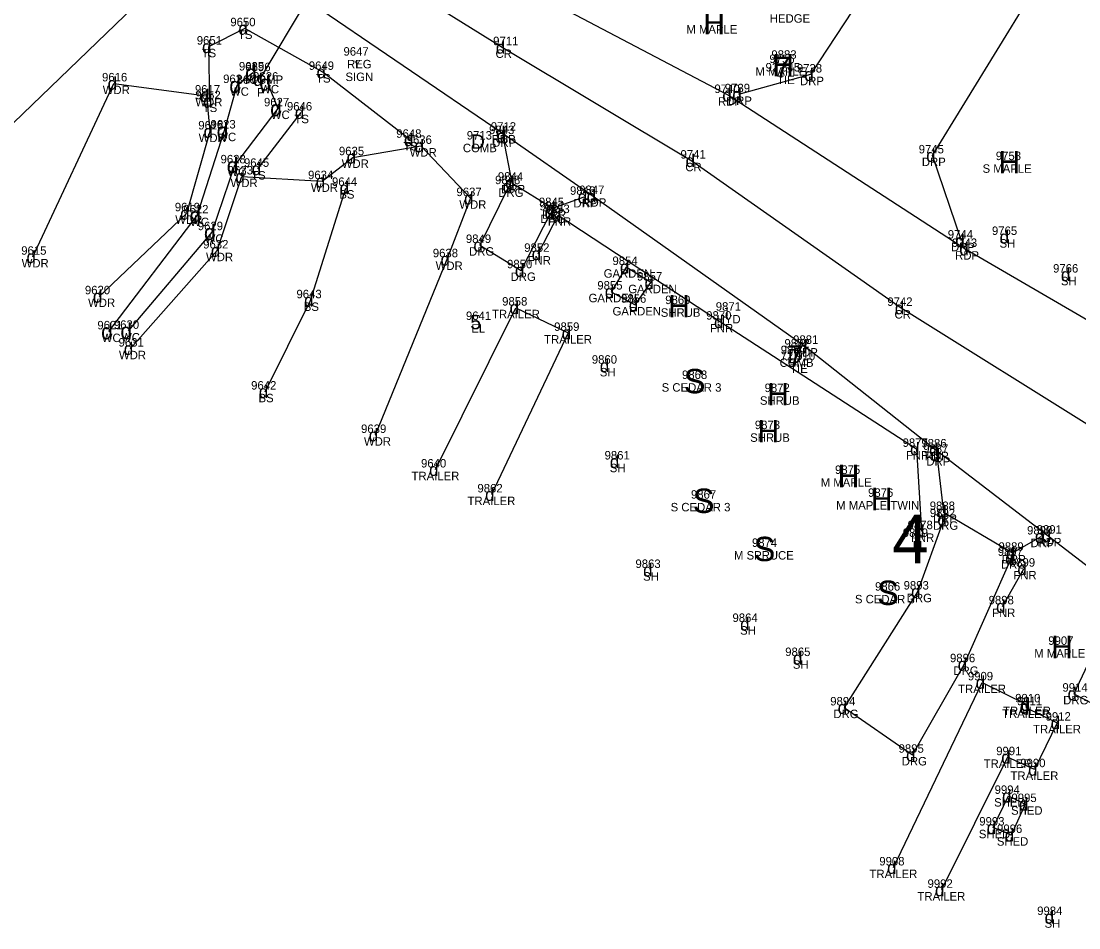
# Model space of a CAD drawing. Extents: x 69415 to 80913, y 7576 to 15059.
# Drawn here: x 78709.2 to 78958.8, y 12276.2 to 12490.3 of the extents above; entities that cross this region are included whole.
import ezdxf

# ---------------------------------------------------------------- set-up
doc = ezdxf.new("R2010")
doc.units = 0
for name, color, linetype in [('Level 1', 7, 'Continuous'), ('Level 11', 7, 'Continuous'), ('Level 12', 7, 'Continuous'), ('Level 13', 7, 'Continuous'), ('Level 14', 7, 'Continuous'), ('Level 15', 7, 'Continuous'), ('Level 16', 7, 'Continuous'), ('Level 43', 7, 'Continuous'), ('Level 46', 7, 'Continuous'), ('Level 47', 7, 'Continuous'), ('Level 48', 7, 'Continuous'), ('Level 59', 7, 'Continuous')]:
    doc.layers.add(name, color=color, linetype=linetype)

msp = doc.modelspace()

# ---------------------------------------------------------------- linework, layer by layer
at = {"layer": 'Level 11'}
for p, q in [((78830.44, 12496.88), (78876.16, 12472.86)), ((78908.51, 12497.6), (78895.52, 12477.7)), ((78924.29, 12458.6), (78948.44, 12498.05)), ((78775.93, 12495.84), (78822.71, 12463.96)), ((78895.52, 12477.7), (78878.52, 12473.04)), ((78876.16, 12472.86), (78932.13, 12436.51)), ((78822.71, 12463.96), (78844.14, 12449.01)), ((78822.87, 12463.15), (78824.95, 12452.16)), ((78931.15, 12438.49), (78924.29, 12458.6)), ((78824.29, 12451.34), (78817.41, 12437.45)), ((78824.95, 12452.16), (78834.62, 12446.16)), ((78834.62, 12446.16), (78842.03, 12448.83)), ((78844.14, 12449.01), (78894.07, 12413.63)), ((78827.2, 12431.48), (78834.2, 12445.15)), ((78817.41, 12437.45), (78827.2, 12431.48)), ((78932.13, 12436.51), (78963.41, 12418.3)), ((78894.07, 12413.63), (78924.98, 12389.17)), ((78924.98, 12389.17), (78951.57, 12368.82)), ((78925.34, 12387.89), (78926.89, 12374.4)), ((78926.89, 12374.4), (78943.13, 12364.78)), ((78926.92, 12372.73), (78920.72, 12355.62)), ((78943.13, 12364.78), (78949.94, 12368.62)), ((78951.57, 12368.82), (78966.36, 12357.45)), ((78931.73, 12338.46), (78942.94, 12363.58)), ((78920.72, 12355.62), (78903.4, 12328.26)), ((78964.1, 12345.2), (78957.65, 12331.51)), ((78919.54, 12317.09), (78931.73, 12338.46)), ((78957.65, 12331.51), (78966.28, 12326.96)), ((78903.4, 12328.26), (78919.54, 12317.09))]:
    msp.add_line(p, q, dxfattribs=at)
at = {"layer": 'Level 12'}
for p, q in [((78831.16, 12435.36), (78835.95, 12444.51)), ((78835.95, 12444.51), (78874.21, 12419.34)), ((78851.99, 12432.25), (78848.42, 12426.45)), ((78857.79, 12428.58), (78851.99, 12432.25)), ((78848.42, 12426.45), (78854.08, 12423.34)), ((78854.08, 12423.34), (78857.79, 12428.58)), ((78874.21, 12419.34), (78920.48, 12389.31)), ((78920.48, 12389.31), (78921.66, 12369.87)), ((78940.79, 12352.13), (78945.82, 12361.02))]:
    msp.add_line(p, q, dxfattribs=at)
at = {"layer": 'Level 13'}
for p, q in [((78806.95, 12384.44), (78825.95, 12422.67)), ((78825.95, 12422.67), (78838.25, 12416.7)), ((78838.25, 12416.7), (78820.17, 12378.55)), ((78915.06, 12290.48), (78935.98, 12334.18)), ((78935.98, 12334.18), (78946.58, 12328.98)), ((78946.58, 12328.98), (78946.35, 12328.31)), ((78946.35, 12328.31), (78953.68, 12324.67)), ((78953.68, 12324.67), (78948.35, 12313.67)), ((78942.01, 12316.51), (78926.37, 12285.2)), ((78948.35, 12313.67), (78942.01, 12316.51)), ((78938.58, 12299.9), (78942.2, 12307.38)), ((78942.2, 12307.38), (78946.18, 12305.45)), ((78946.18, 12305.45), (78942.83, 12298.15)), ((78942.83, 12298.15), (78938.58, 12299.9))]:
    msp.add_line(p, q, dxfattribs=at)
at = {"layer": 'Level 14'}
for p, q in [((78711.91, 12434.67), (78731.05, 12475.6)), ((78731.05, 12475.6), (78752.91, 12472.73)), ((78752.91, 12472.73), (78753.7, 12464.26)), ((78753.7, 12464.26), (78748.18, 12444.94)), ((78787.47, 12458.17), (78803.51, 12460.85)), ((78803.51, 12460.85), (78815.21, 12448.52)), ((78780.19, 12452.52), (78787.47, 12458.17)), ((78755.43, 12436.15), (78761.23, 12453.63)), ((78761.23, 12453.63), (78780.19, 12452.52)), ((78815.21, 12448.52), (78809.64, 12434.08)), ((78748.18, 12444.94), (78727.59, 12425.34)), ((78734.88, 12412.99), (78755.43, 12436.15)), ((78809.64, 12434.08), (78792.7, 12392.59))]:
    msp.add_line(p, q, dxfattribs=at)
at = {"layer": 'Level 15'}
msp.add_line((78753.41, 12510.83), (78705.11, 12464.18), dxfattribs=at)
at = {"layer": 'Level 16'}
for p, q in [((78760.14, 12475.21), (78763.86, 12478.18)), ((78757.14, 12464.48), (78760.14, 12475.21)), ((78767.27, 12475.77), (78769.78, 12469.71)), ((78769.78, 12469.71), (78759.53, 12456.25)), ((78750.72, 12444.43), (78757.14, 12464.48)), ((78759.53, 12456.25), (78754.16, 12440.47)), ((78729.88, 12417.05), (78750.72, 12444.43)), ((78754.16, 12440.47), (78734.43, 12417.18))]:
    msp.add_line(p, q, dxfattribs=at)
at = {"layer": 'Level 48'}
for p, q in [((78784.6, 12507.97), (78822.7, 12484.15)), ((78761.93, 12488.62), (78753.35, 12484.29)), ((78780.37, 12478.32), (78761.93, 12488.62)), ((78753.35, 12484.29), (78753.61, 12471.37)), ((78822.7, 12484.15), (78867.49, 12457.38)), ((78801, 12462.29), (78780.37, 12478.32)), ((78765.05, 12455.43), (78775.25, 12468.73)), ((78867.49, 12457.38), (78916.88, 12422.6)), ((78777.44, 12424.4), (78785.82, 12450.93)), ((78766.75, 12402.84), (78777.44, 12424.4)), ((78916.88, 12422.6), (79048.1, 12340.71))]:
    msp.add_line(p, q, dxfattribs=at)
at = {"layer": 'Level 59'}
msp.add_line((78803.72, 12540.95), (78765.44, 12476.52), dxfattribs=at)

# ---------------------------------------------------------------- texts
at = {"layer": 'Level 1'}
for p in [(78887.01, 12476.95), (78890.09, 12408.77)]:
    msp.add_text('7', height=5, dxfattribs=at).set_placement(p)
at = {"layer": 'Level 14'}
for s, height, p in [('H', 5.3, (78870.17, 12487.25)), ('H', 5.3, (78886.45, 12477.29)), ('H', 5.3, (78939.84, 12454.37)), ('H', 5.3, (78861.86, 12420.37)), ('S', 5.75, (78865.58, 12402.46)), ('H', 5.3, (78885.26, 12399.6)), ('H', 5.3, (78882.96, 12390.85)), ('H', 5.3, (78901.88, 12380.27)), ('S', 5.75, (78867.7, 12374.21)), ('H', 5.3, (78909.73, 12374.86)), ('S', 5.75, (78882.05, 12362.83)), ('S', 5.75, (78911.2, 12352.48)), ('H', 5.3, (78952.3, 12339.91))]:
    msp.add_text(s, height=height, dxfattribs=at).set_placement(p)
at = {"layer": 'Level 15'}
for s, height, p in [('D', 3.4, (78815.33, 12460.18)), ('J', 2.26, (78874.68, 12420.33)), ('5', 3.4, (78815.18, 12417.57)), ('D', 3.4, (78890.1, 12409.5)), ('4', 11.5, (78914.79, 12362.3))]:
    msp.add_text(s, height=height, dxfattribs=at).set_placement(p)
at = {"layer": 'Level 43'}
msp.add_text('Y', height=1.7, dxfattribs=at).set_placement((78787.7, 12479.33))
at = {"layer": 'Level 46'}
for s, p in [('HEDGE', (78885.87, 12489.96)), ('9650', (78758.53, 12489.12)), ('M MAPLE', (78866.17, 12487.4)), ('9651', (78750.61, 12484.79)), ('TS', (78760.34, 12486.12)), ('9711', (78820.57, 12484.65)), ('TS', (78751.76, 12481.79)), ('9647', (78785.24, 12482.18)), ('CR', (78821.13, 12481.65)), ('9756', (78885.79, 12480.44)), ('9883', (78886.25, 12481.45)), ('9625', (78760.55, 12478.68)), ('9696', (78762.08, 12478.52)), ('9649', (78777.05, 12478.82)), ('REG', (78786.08, 12479.18)), ('M MAPLE', (78882.46, 12477.44)), ('92.345', (78884.87, 12478.45)), ('9738', (78892.26, 12478.2)), ('9616', (78728.25, 12476.1)), ('9624', (78756.83, 12475.71)), ('36CGMP', (78760.01, 12475.52)), ('WC', (78762.17, 12475.68)), ('9626', (78763.91, 12476.27)), ('TS', (78778.78, 12475.82)), ('SIGN', (78785.71, 12476.18)), ('TIE', (78887.59, 12475.45)), ('DRP', (78893.01, 12475.2)), ('WDR', (78728.41, 12473.1)), ('9617', (78750.17, 12473.23)), ('9652', (78750.3, 12471.87)), ('WC', (78758.45, 12472.71)), ('P', (78764.82, 12472.52)), ('WC', (78765.58, 12473.27)), ('9740', (78872.81, 12473.36)), ('9739', (78875.26, 12473.54)), ('WDR', (78750.27, 12470.23)), ('9627', (78766.47, 12470.21)), ('RDP', (78873.65, 12470.36)), ('DRP', (78876.01, 12470.54)), ('TS', (78752.02, 12468.87)), ('WC', (78768.09, 12467.21)), ('9646', (78771.89, 12469.23)), ('9618', (78750.96, 12464.76)), ('9623', (78753.84, 12464.98)), ('TS', (78773.66, 12466.23)), ('9712', (78820.02, 12464.46)), ('WC', (78755.45, 12461.98)), ('9648', (78797.69, 12462.79)), ('9713', (78814.34, 12462.38)), ('9843', (78819.61, 12463.65)), ('WDR', (78751.06, 12461.76)), ('TS', (78799.41, 12459.79)), ('9636', (78800.15, 12461.35)), ('COMB', (78813.42, 12459.38)), ('RDP', (78820.2, 12461.46)), ('DRP', (78820.36, 12460.65)), ('9635', (78784.16, 12458.67)), ('WDR', (78800.87, 12458.35)), ('9741', (78864.8, 12457.88)), ('9745', (78921.03, 12459.1)), ('9758', (78939.23, 12457.52)), ('9628', (78756.22, 12456.75)), ('9645', (78761.74, 12455.93)), ('WDR', (78784.83, 12455.67)), ('CR', (78865.93, 12454.88)), ('DRP', (78921.77, 12456.1)), ('S MAPLE', (78936.1, 12454.52)), ('WC', (78757.84, 12453.75)), ('9633', (78757.92, 12454.13)), ('TS', (78763.46, 12452.93)), ('9634', (78776.88, 12453.02)), ('9848', (78821.03, 12451.84)), ('9844', (78821.69, 12452.66)), ('WDR', (78758.59, 12451.13)), ('WDR', (78777.55, 12450.02)), ('9644', (78782.52, 12451.43)), ('DRP', (78822.44, 12449.66)), ('9846', (78838.71, 12449.33)), ('9847', (78840.88, 12449.51)), ('BS', (78784.26, 12448.43)), ('9637', (78811.91, 12449.02)), ('DRG', (78821.78, 12448.84)), ('9619', (78745.43, 12445.44)), ('9622', (78747.41, 12444.93)), ('WDR', (78812.58, 12446.02)), ('9845', (78831.36, 12446.66)), ('9851', (78831.51, 12445.65)), ('9853', (78832.69, 12445.01)), ('DRP', (78839.51, 12446.33)), ('RDP', (78841.63, 12446.51)), ('WDR', (78745.54, 12442.44)), ('WC', (78749.03, 12441.93)), ('DRG', (78831.69, 12442.65)), ('DRP', (78832.11, 12443.66)), ('FNR', (78833.49, 12442.01)), ('9629', (78750.85, 12440.97)), ('9765', (78938.31, 12439.85)), ('WC', (78752.47, 12437.97)), ('9849', (78814.14, 12437.95)), ('9744', (78927.89, 12438.99)), ('9743', (78928.87, 12437.01)), ('SH', (78940.11, 12436.85)), ('9615', (78709.17, 12435.17)), ('9632', (78752.12, 12436.65)), ('9638', (78806.33, 12434.58)), ('DRG', (78814.89, 12434.95)), ('9852', (78827.9, 12435.86)), ('DRP', (78928.64, 12435.99)), ('WDR', (78709.27, 12432.17)), ('WDR', (78752.79, 12433.65)), ('9850', (78823.85, 12431.98)), ('FNR', (78828.7, 12432.86)), ('9854', (78848.73, 12432.75)), ('RDP', (78929.62, 12434.01)), ('WDR', (78807, 12431.58)), ('GARDEN', (78846.66, 12429.75)), ('9766', (78952.74, 12430.96)), ('DRG', (78824.69, 12428.98)), ('9855', (78845.16, 12426.95)), ('9857', (78854.53, 12429.08)), ('SH', (78954.59, 12427.96)), ('9620', (78724.2, 12425.84)), ('9643', (78774.14, 12424.9)), ('GARDEN', (78852.46, 12426.08)), ('WDR', (78724.95, 12422.84)), ('BS', (78775.88, 12421.9)), ('9858', (78822.69, 12423.17)), ('GARDEN', (78843.09, 12423.95)), ('9856', (78850.77, 12423.84)), ('9869', (78861.19, 12423.52)), ('9871', (78873.12, 12421.96)), ('9742', (78913.62, 12423.1)), ('9641', (78814.14, 12419.77)), ('TRAILER', (78820.3, 12420.17)), ('GARDEN', (78848.75, 12420.84)), ('SHRUB', (78860.14, 12420.52)), ('9870', (78870.86, 12419.84)), ('CR', (78915.31, 12420.1)), ('9621', (78727.14, 12417.55)), ('9630', (78731.04, 12417.68)), ('9859', (78834.98, 12417.2)), ('HYD', (78873.33, 12418.96)), ('WC', (78728.18, 12414.55)), ('WC', (78732.74, 12414.68)), ('EL', (78815.42, 12416.77)), ('FNR', (78871.74, 12416.84)), ('9631', (78732.14, 12413.49)), ('TRAILER', (78832.6, 12414.2)), ('9882', (78889.33, 12413.27)), ('9881', (78891.38, 12414.13)), ('WDR', (78732.24, 12410.49)), ('9860', (78843.86, 12409.45)), ('72.910', (78888.42, 12410.27)), ('9880', (78888.45, 12411.7)), ('RDP', (78891.56, 12411.13)), ('COMB', (78888.18, 12408.7)), ('TIE', (78890.67, 12407.27)), ('SH', (78845.74, 12406.45)), ('9868', (78865.15, 12405.84)), ('9642', (78763.44, 12403.34)), ('S CEDAR 3', (78860.34, 12402.84)), ('9872', (78884.65, 12402.75)), ('BS', (78765.19, 12400.34)), ('SHRUB', (78883.54, 12399.75)), ('9639', (78789.39, 12393.09)), ('9873', (78882.35, 12394)), ('WDR', (78790.07, 12390.09)), ('SHRUB', (78881.24, 12391)), ('9877', (78917.22, 12389.81)), ('9886', (78921.66, 12389.67)), ('9887', (78922.08, 12388.39)), ('9640', (78803.55, 12384.94)), ('9861', (78846.87, 12386.83)), ('FNR', (78918.02, 12386.81)), ('RDP', (78922.46, 12386.67)), ('DRP', (78922.83, 12385.39)), ('TRAILER', (78801.3, 12381.94)), ('SH', (78848.1, 12383.83)), ('9875', (78901.27, 12383.42)), ('M MAPLE', (78897.88, 12380.42)), ('9862', (78816.86, 12379.05)), ('9867', (78867.26, 12377.58)), ('9876', (78909.07, 12378.01)), ('TRAILER', (78814.52, 12376.05)), ('S CEDAR 3', (78862.46, 12374.58)), ('M MAPLE TWIN', (78901.55, 12375.01)), ('9888', (78923.63, 12374.9)), ('9892', (78923.66, 12373.23)), ('9878', (78918.4, 12370.37)), ('DRP', (78924.38, 12371.9)), ('DRG', (78924.41, 12370.23)), ('9879', (78917.28, 12368.55)), ('FNR', (78919.2, 12367.37)), ('9890', (78946.6, 12369.12)), ('9891', (78948.88, 12369.32)), ('9874', (78881.66, 12366.2)), ('LI', (78919.65, 12365.55)), ('9889', (78939.86, 12365.28)), ('DRP', (78947.43, 12366.12)), ('RDP', (78949.06, 12366.32)), ('M SPRUCE', (78877.42, 12363.2)), ('9897', (78939.68, 12364.08)), ('DRP', (78940.62, 12362.28)), ('9863', (78854.16, 12361.22)), ('DRG', (78940.43, 12361.08)), ('9899', (78942.55, 12361.52)), ('SH', (78855.96, 12358.22)), ('FNR', (78943.36, 12358.52)), ('9866', (78910.71, 12355.86)), ('9893', (78917.46, 12356.12)), ('S CEDAR 3', (78905.97, 12352.86)), ('DRG', (78918.21, 12353.12)), ('9898', (78937.53, 12352.63)), ('FNR', (78938.33, 12349.63)), ('9864', (78877.06, 12348.47)), ('SH', (78878.86, 12345.47)), ('9907', (78951.61, 12343.06)), ('9865', (78889.51, 12340.42)), ('M MAPLE', (78948.3, 12340.06)), ('SH', (78891.31, 12337.42)), ('9896', (78928.41, 12338.96)), ('DRG', (78929.22, 12335.96)), ('9909', (78932.63, 12334.68)), ('9914', (78954.95, 12332.01)), ('TRAILER', (78930.33, 12331.68)), ('9910', (78943.8, 12329.48)), ('9894', (78900.14, 12328.76)), ('9911', (78944.22, 12328.81)), ('DRG', (78955.14, 12329.01)), ('DRG', (78900.89, 12325.76)), ('TRAILER', (78940.7, 12325.81)), ('TRAILER', (78940.93, 12326.48)), ('9912', (78950.98, 12325.17)), ('TRAILER', (78948.03, 12322.17)), ('9895', (78916.28, 12317.59)), ('9991', (78939.32, 12317.01)), ('DRG', (78917.02, 12314.59)), ('TRAILER', (78936.36, 12314.01)), ('9990', (78945, 12314.17)), ('TRAILER', (78942.7, 12311.17)), ('9994', (78938.94, 12307.88)), ('SHED', (78938.83, 12304.88)), ('9995', (78942.92, 12305.95)), ('SHED', (78942.82, 12302.95)), ('9993', (78935.32, 12300.4)), ('SHED', (78935.22, 12297.4)), ('9996', (78939.52, 12298.65)), ('SHED', (78939.47, 12295.65)), ('9908', (78911.72, 12290.98)), ('TRAILER', (78909.41, 12287.98)), ('9992', (78923.11, 12285.7)), ('TRAILER', (78920.73, 12282.7)), ('9984', (78948.99, 12279.27)), ('SH', (78950.74, 12276.27))]:
    msp.add_text(s, height=2, dxfattribs=at).set_placement(p)
at = {"layer": 'Level 47'}
for height, p in [(3, (78760.43, 12487.12)), (3, (78751.85, 12482.79)), (3, (78821.2, 12482.65)), (3.7, (78762.01, 12476.33)), (3, (78778.87, 12476.82)), (3, (78894.02, 12476.2)), (3, (78729.55, 12474.1)), (3.7, (78758.29, 12473.36)), (3, (78763.94, 12475.02)), (3.7, (78765.42, 12473.92)), (3, (78751.41, 12471.23)), (3, (78874.66, 12471.36)), (3, (78877.02, 12471.54)), (3, (78752.11, 12469.87)), (3.7, (78767.93, 12467.86)), (3, (78773.75, 12467.23)), (3.7, (78755.29, 12462.63)), (3, (78752.2, 12462.76)), (3, (78799.5, 12460.79)), (3, (78821.21, 12462.46)), (3, (78821.37, 12461.65)), (3, (78802.01, 12459.35)), (3, (78785.97, 12456.67)), (3, (78865.99, 12455.88)), (3, (78922.79, 12457.1)), (3.7, (78757.68, 12454.4)), (3, (78763.55, 12453.93)), (3, (78759.73, 12452.13)), (3, (78778.69, 12451.02)), (3, (78823.45, 12450.66)), (3, (78784.32, 12449.43)), (3, (78822.79, 12449.84)), (3, (78813.71, 12447.02)), (3, (78840.53, 12447.33)), (3, (78842.64, 12447.51)), (3, (78746.68, 12443.44)), (3.7, (78748.87, 12442.58)), (3, (78832.7, 12443.65)), (3, (78833.12, 12444.66)), (3, (78834.45, 12443.01)), (3.7, (78752.31, 12438.62)), (3, (78815.91, 12435.95)), (3, (78929.65, 12436.99)), (3, (78940.12, 12437.85)), (3, (78753.93, 12434.65)), (3, (78829.66, 12433.86)), (3, (78930.63, 12435.01)), (3, (78710.41, 12433.17)), (3, (78808.14, 12432.58)), (3, (78850.49, 12430.75)), (3, (78825.7, 12429.98)), (3, (78954.6, 12428.96)), (3, (78856.29, 12427.08)), (3, (78726.09, 12423.84)), (3, (78846.92, 12424.95)), (3, (78775.94, 12422.9)), (3, (78824.45, 12421.17)), (3, (78852.58, 12421.84)), (3, (78915.38, 12421.1)), (3.7, (78728.03, 12415.2)), (3.7, (78732.58, 12415.33)), (3, (78872.71, 12417.84)), (3, (78836.75, 12415.2)), (3, (78733.38, 12411.49)), (3, (78892.57, 12412.13)), (3, (78845.75, 12407.45)), (3, (78765.25, 12401.34)), (3, (78791.2, 12391.09)), (3, (78918.98, 12387.81)), (3, (78923.48, 12387.67)), (3, (78923.84, 12386.39)), (3, (78848.11, 12384.83)), (3, (78805.45, 12382.94)), (3, (78818.67, 12377.05)), (3, (78925.39, 12372.9)), (3, (78925.42, 12371.23)), (3, (78920.16, 12368.37)), (3, (78948.44, 12367.12)), (3, (78950.07, 12367.32)), (3, (78941.63, 12363.28)), (3, (78941.44, 12362.08)), (3, (78855.97, 12359.22)), (3, (78944.32, 12359.52)), (3, (78919.22, 12354.12)), (3, (78939.29, 12350.63)), (3, (78878.87, 12346.47)), (3, (78891.32, 12338.42)), (3, (78930.23, 12336.96)), (3, (78934.48, 12332.68)), (3, (78956.15, 12330.01)), (3, (78901.9, 12326.76)), (3, (78944.85, 12326.81)), (3, (78945.08, 12327.48)), (3, (78952.18, 12323.17)), (3, (78918.04, 12315.59)), (3, (78940.51, 12315.01)), (3, (78946.85, 12312.17)), (3, (78940.7, 12305.88)), (3, (78944.68, 12303.95)), (3, (78937.08, 12298.4)), (3, (78941.33, 12296.65)), (3, (78913.56, 12288.98)), (3, (78924.87, 12283.7)), (3, (78950.75, 12277.27))]:
    msp.add_text('d', height=height, dxfattribs=at).set_placement(p)

doc.saveas('drawing.dxf')
